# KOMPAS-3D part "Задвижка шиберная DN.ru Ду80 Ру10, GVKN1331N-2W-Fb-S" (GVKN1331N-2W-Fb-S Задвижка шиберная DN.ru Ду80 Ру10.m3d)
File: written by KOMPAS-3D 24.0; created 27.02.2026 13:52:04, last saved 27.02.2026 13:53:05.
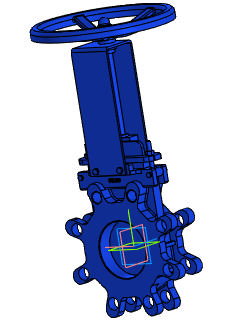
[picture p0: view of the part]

Document properties: Автор: R2D2; Полное имя файла: GVKN1331N-2W-Fb-S Задвижка шиберная DN.ru Ду80 Ру10.cdw

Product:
- Part/product: Задвижка шиберная DN.ru Ду80 Ру10  | designation GVKN1331N-2W-Fb-S
    Масса: 9.5
    Раздел спецификации: Прочие изделия
    Форматы листов документа: A3
    Примечание: D040-07823
    additional columns: D040-07823

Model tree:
1. Операция без истории:1

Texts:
  GVKN1331N-2W-Fb-S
